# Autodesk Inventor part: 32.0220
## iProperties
Created: 2012-10
Part Number: 32.0220
Material: Steel
Document SubType Name: Modeling
Designer: Administrator
Density: 7.85 g/cm^3
Description: C-SECTION RAIL
Author: Administrator
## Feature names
1. Extrusion2
